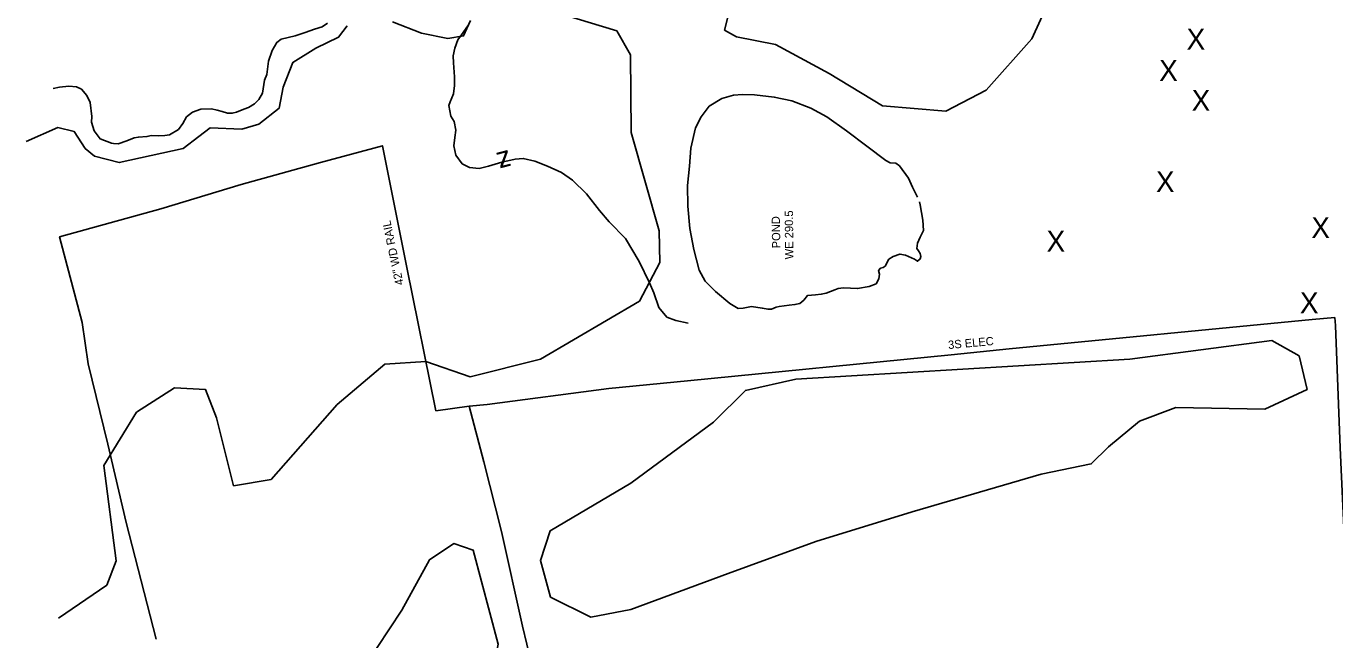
# Model space of a CAD drawing. Extents: x 2030130 to 2036320, y 723205 to 762423.
# Drawn here: x 2033444 to 2034073, y 737377 to 737672 of the extents above; entities that cross this region are included whole.
import ezdxf

# ---------------------------------------------------------------- set-up
doc = ezdxf.new("R2010")
doc.units = 0
for name, color, linetype in [('Draft_Station Tics Major', 7, 'Continuous'), ('Exist Terrain Model Ground Surface', 7, 'Continuous'), ('Old_Level_28', 7, 'Continuous'), ('Prop Alignment Horizontal', 7, 'Continuous'), ('Prop Alignment Vertical', 7, 'Continuous')]:
    doc.layers.add(name, color=color, linetype=linetype)

msp = doc.modelspace()

# ---------------------------------------------------------------- linework, layer by layer
at = {"layer": 'Draft_Station Tics Major'}
for points in [[(2033943.63, 737702.7), (2033926.93, 737665.92), (2033904.97, 737641.26), (2033885.57, 737631.2), (2033855.14, 737633.82), (2033829.51, 737649.23), (2033803.66, 737663.3), (2033785.04, 737666.93), (2033779.15, 737670.19), (2033780.87, 737676.32), (2033819.33, 737695.93)], [(2033701.6, 737677.71), (2033727.44, 737669.82), (2033734.05, 737658.24), (2033734.33, 737620.96), (2033747.83, 737573.65), (2033748.16, 737558.39), (2033738.36, 737539.94), (2033690.82, 737511.97), (2033656.98, 737503.49), (2033635.76, 737510.86), (2033616.03, 737509.69), (2033593.07, 737490.27), (2033561.32, 737454.12), (2033543.28, 737451.16), (2033535.15, 737483.84), (2033529.75, 737497.51), (2033514.91, 737498.32), (2033496.61, 737486.5), (2033481, 737460.88), (2033486.82, 737415.14), (2033482.43, 737403.49), (2033459.19, 737387.56)], [(2033619.62, 737674.1), (2033633.56, 737668.67), (2033646.23, 737666.18), (2033653.8, 737667.32), (2033657.1, 737674.75)], [(2033443.6, 737616.62), (2033458.86, 737623.33), (2033466.72, 737621.36), (2033471.89, 737613.3), (2033476.42, 737609.5), (2033488.3, 737606.45), (2033519, 737613.29), (2033526.51, 737619.05), (2033532.03, 737623.14), (2033547.27, 737622.51), (2033555.45, 737624.98), (2033565.13, 737632.61), (2033567.16, 737642.79), (2033571.75, 737654.63), (2033582.76, 737661.45), (2033593.73, 737666.73), (2033597.94, 737672.21)], [(2033734.26, 737391.77), (2033715.04, 737388.08), (2033695.63, 737397.72), (2033690.73, 737415.23), (2033695.39, 737429.58), (2033734.28, 737452.4), (2033773.94, 737481.76), (2033789.25, 737496.96), (2033813.54, 737502.44), (2033974.08, 737512.08), (2034042.3, 737520.92), (2034055.41, 737513.59), (2034059.2, 737497.46), (2034038.84, 737488.01), (2033996.19, 737488.85), (2033978.62, 737482.22), (2033963.79, 737469.9), (2033955.44, 737461.65), (2033931.35, 737456.74), (2033869.43, 737438.65), (2033823.06, 737424.35), (2033780.91, 737408.96), (2033734.26, 737391.77)], [(2033606.43, 737364.57), (2033624.2, 737391.48), (2033637.45, 737415.62), (2033649.06, 737423.39), (2033658.43, 737420.22), (2033670.45, 737375.08), (2033668.41, 737364.71), (2033655.42, 737356.01), (2033627.36, 737347.36), (2033612.67, 737346.82), (2033605.65, 737357.84), (2033606.43, 737364.57)]]:
    msp.add_lwpolyline(points, dxfattribs=at)
at = {"layer": 'Exist Terrain Model Ground Surface'}
for points in [[(2033640.48, 737487.18), (2033626.49, 737555.99), (2033614.82, 737614.55), (2033585.11, 737606.47), (2033546.99, 737595.91), (2033508.38, 737584.24), (2033459.68, 737570.85), (2033470.48, 737529.65), (2033473.37, 737509.82), (2033482.88, 737471.2), (2033491.63, 737433.52), (2033506.12, 737377.49)], [(2034062.21, 737090.5), (2034065.17, 737122.25), (2034073.42, 737152.81), (2034089.84, 737195.16), (2034087, 737244.85), (2034083.17, 737305.75), (2034078.65, 737392.73), (2034075.14, 737469.41), (2034072.89, 737528.16), (2034072.47, 737531.99), (2034061.59, 737531.06), (2033915.98, 737516.91), (2033888.14, 737514.16), (2033761.39, 737501.64), (2033723.65, 737497.93), (2033665.21, 737490.19)], [(2033656.52, 737489.39), (2033640.48, 737487.18)], [(2033675.98, 737339.32), (2033672.69, 737354.35), (2033688.31, 737357.81), (2033682.15, 737383.74), (2033672.12, 737429.28), (2033663.5, 737462.72), (2033656.52, 737489.39), (2033665.21, 737490.19)]]:
    msp.add_lwpolyline(points, dxfattribs=at)
at = {"layer": 'Prop Alignment Horizontal'}
for points in [[(2033588.41, 737673.48), (2033585.8, 737671.79), (2033582.16, 737670.58), (2033577.73, 737669.07), (2033572.96, 737667.37), (2033566.23, 737665.8), (2033564.02, 737664.22), (2033561.8, 737660.29), (2033560.02, 737655.23), (2033559.24, 737648.82), (2033558.18, 737646.04), (2033557.15, 737639.9), (2033555.49, 737636.81), (2033553.4, 737634.77), (2033550.39, 737632.89), (2033548.27, 737632.16), (2033544.62, 737630.63), (2033542.64, 737630.16), (2033540.42, 737630.23), (2033537.75, 737630.96), (2033535.41, 737631.68), (2033532.61, 737632.29), (2033527.55, 737632.11), (2033523.58, 737630.78), (2033520.63, 737628.44), (2033518.83, 737625.28), (2033516.78, 737622.32), (2033512.51, 737619.76), (2033510.28, 737619.49), (2033507.19, 737619.39), (2033503.85, 737619.48), (2033501.67, 737618.96), (2033497.54, 737618.75), (2033495.43, 737618.35), (2033491.91, 737616.94), (2033487.87, 737615.49), (2033485.51, 737615.62), (2033484.54, 737615.78), (2033479.09, 737617.9), (2033476.32, 737621.79), (2033474.93, 737625.89), (2033475.14, 737628.64), (2033474.28, 737635.28), (2033472.74, 737638.74), (2033470.14, 737641.76), (2033467.81, 737642.88), (2033464.09, 737643.18), (2033459.68, 737642.66), (2033456.58, 737642.09)], [(2033761.71, 737529.24), (2033755.89, 737530.53), (2033751.52, 737532.17), (2033747.71, 737536.89), (2033745.28, 737543.94), (2033743.24, 737548.74), (2033738.27, 737558.96), (2033731.6, 737569.96), (2033723.87, 737578.08), (2033719.09, 737583.49), (2033712.93, 737591.5), (2033706.14, 737597.96), (2033700.91, 737601.73), (2033694.09, 737604.82), (2033688.03, 737607.24), (2033682.53, 737608.45), (2033678.57, 737608.1), (2033672.28, 737606.71), (2033665.83, 737604.79), (2033661.26, 737603.67), (2033656.73, 737604.19), (2033653.15, 737605.81), (2033650.11, 737609.98), (2033649.12, 737614.55), (2033649.63, 737618.49), (2033650.07, 737622.1), (2033649.33, 737626.2), (2033647.69, 737628.82), (2033646.72, 737633.92), (2033647.3, 737635.62), (2033648.99, 737639.45), (2033649.5, 737643.45), (2033649.42, 737647.67), (2033649.03, 737654.47), (2033648.79, 737657.83), (2033649.69, 737661.49), (2033651.06, 737665.54), (2033652.77, 737667.92), (2033656.14, 737672.7)], [(2033872.02, 737589.84), (2033869.62, 737594.6), (2033867.59, 737599.03), (2033863.4, 737604.89), (2033861.61, 737606.18), (2033858.88, 737606.39), (2033856.69, 737607.43), (2033847.63, 737614.41), (2033837.93, 737621.73), (2033828.35, 737628.53), (2033820.78, 737632.66), (2033811.62, 737636.12), (2033803.13, 737637.93), (2033793.71, 737639.11), (2033787.85, 737639.22), (2033783.54, 737638.95), (2033777.95, 737637.29), (2033771.91, 737633.61), (2033767.98, 737628.45), (2033765.21, 737623.11), (2033763.04, 737613.4), (2033762.4, 737604.74), (2033761.48, 737595.51), (2033761.65, 737585.47), (2033762.51, 737574.82), (2033764.44, 737564.65), (2033767.08, 737554.8), (2033769.87, 737549.5), (2033774.87, 737544.53), (2033781.75, 737538.73), (2033785.72, 737536.4), (2033788.14, 737536.59), (2033792.2, 737537.25), (2033797.33, 737536.58), (2033800.18, 737535.98), (2033801.88, 737536.12), (2033803.99, 737536.97), (2033805.5, 737537.32), (2033810.22, 737538.03), (2033813.09, 737538.21), (2033815.46, 737538.8), (2033817.33, 737540.44), (2033819.09, 737542.6), (2033823.01, 737543.01), (2033825.75, 737543.19), (2033828.12, 737543.78), (2033832.2, 737545.29), (2033833.92, 737545.95), (2033836.4, 737546.27), (2033843.18, 737545.95), (2033848.68, 737546.9), (2033852.11, 737548.17), (2033853.35, 737550.67), (2033853.68, 737552.82), (2033853.27, 737554.59), (2033854.15, 737555.67), (2033855.46, 737556.02), (2033856.46, 737556.78), (2033858.12, 737560.06), (2033860.25, 737561.3), (2033863.54, 737562.51), (2033866.13, 737562.04), (2033869.16, 737560.78), (2033870.6, 737560.09), (2033872.01, 737559.07), (2033873.28, 737560.2), (2033873.51, 737561.37), (2033873.29, 737562.75), (2033872.48, 737564.01), (2033871.67, 737565.27), (2033872, 737567.74), (2033873.25, 737570.57), (2033874.78, 737573.85), (2033874.47, 737578.82), (2033873.31, 737586.15), (2033872.96, 737587.66)]]:
    msp.add_lwpolyline(points, dxfattribs=at)

# ---------------------------------------------------------------- texts
at = {"layer": 'Draft_Station Tics Major'}
for p in [(2034001.31, 737660.8), (2033988.13, 737645.73), (2034003.74, 737631.38), (2033986.59, 737592.29), (2034061.25, 737570.24), (2033934.01, 737563.69), (2034055.77, 737534.1)]:
    msp.add_text('X', height=10, dxfattribs=at).set_placement(p)
at = {"layer": 'Old_Level_28'}
for s, rotation, p in [('42" WD RAIL', 101.69589, (2033625.04, 737547.98)), ('3S ELEC', 5.15183, (2033886.85, 737516.85))]:
    msp.add_text(s, height=4, rotation=rotation, dxfattribs=at).set_placement(p)
at = {"layer": 'Prop Alignment Horizontal'}
msp.add_text('z', height=10, rotation=194.57176, dxfattribs=at).set_placement((2033675.39, 737612.66))
at = {"layer": 'Prop Alignment Vertical'}
for s, rotation, p in [('POND', 91.10913, (2033806.12, 737565.31)), ('WE 290.5', 90.4706, (2033812.34, 737560.02))]:
    msp.add_text(s, height=4, rotation=rotation, dxfattribs=at).set_placement(p)

doc.saveas('drawing.dxf')
